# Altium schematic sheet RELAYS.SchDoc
size A4; Revision: V1.2; SheetNumber: 3; SheetTotal: 10
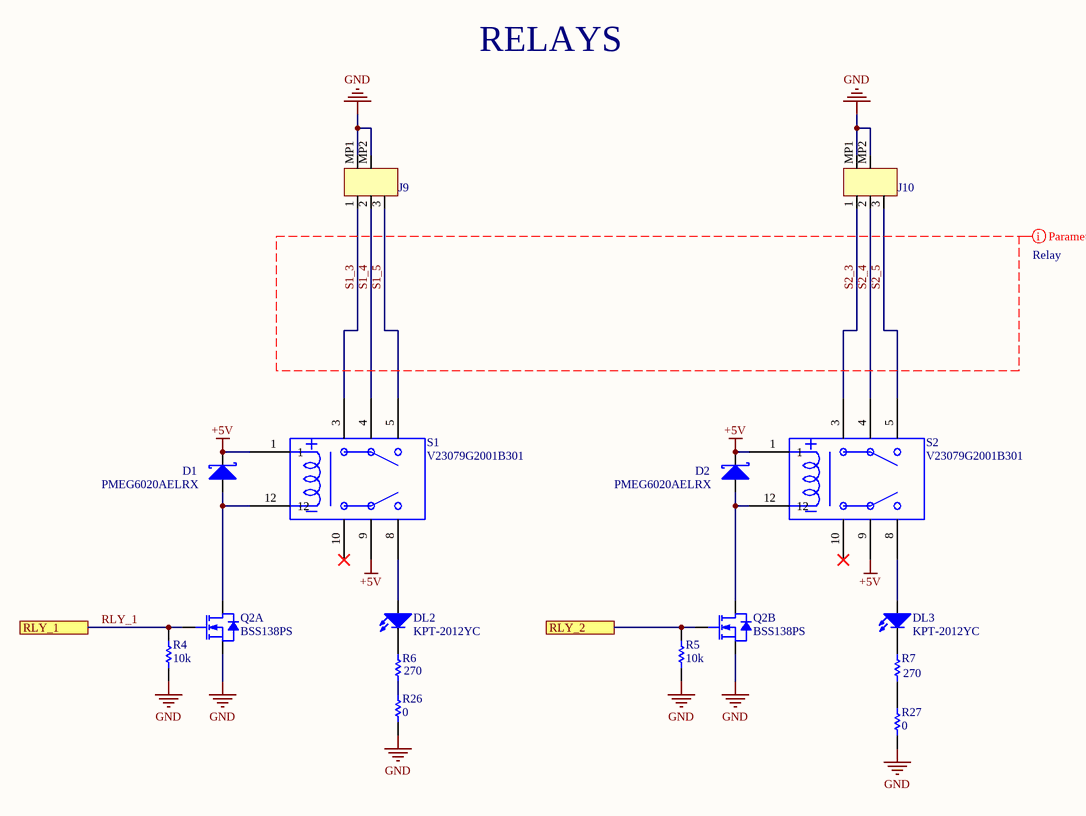
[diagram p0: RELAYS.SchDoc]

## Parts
D1  PMEG6020AELRX  [SOD123-1]
D2  PMEG6020AELRX  [SOD123-1]
DL2  KPT-2012YC  [CHIPLED_0805]
DL3  KPT-2012YC  [CHIPLED_0805]
J9  1771101  [1771101-Footprint-1]  (value not drawn)
J10  1771101  [1771101-Footprint-1]  (value not drawn)
Q2  BSS138PS  [SOT363]  (parts A,B of 2)
R4  value 10k  [RES-0402]  (hidden comment: CRCW040210K0FKED)
R5  value 10k  [RES-0402]  (hidden comment: CRCW040210K0FKED)
R6  value 270  [RES-0402]  (hidden comment: RC0402JR-07270RL)
R7  value 270  [RES-0402]  (hidden comment: RC0402JR-07270RL)
R26  value 0  [RES-0402]  (hidden comment: CRCW04020000Z0EDC)
R27  value 0  [RES-0402]  (hidden comment: CRCW04020000Z0EDC)
S1  V23079G2001B301  [EE2-5NU-L-Footprint-1]
S2  V23079G2001B301  [EE2-5NU-L-Footprint-1]

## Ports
RLY_1, RLY_2

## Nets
+5V: D1.C D2.C S1.1 S1.9 S2.1 S2.9
GND: J9.MP1 J9.MP2 J10.MP1 J10.MP2 Q2.1(S) Q2.4(S) R4.2 R5.2 R26.1 R27.1
RLY_1: Q2.2(G) R4.1 ; port RLY_1
RLY_2: Q2.5(G) R5.1 ; port RLY_2
S1_3: J9.1 S1.3
S1_4: J9.2 S1.4
S1_5: J9.3 S1.5
S2_3: J10.1 S2.3
S2_4: J10.2 S2.4
S2_5: J10.3 S2.5
NetD1_A: D1.A Q2.6(D) S1.12
NetD2_A: D2.A Q2.3(D) S2.12
NetDL2_A: DL2.A S1.8
NetDL2_C: DL2.C R6.2
NetDL3_A: DL3.A S2.8
NetDL3_C: DL3.C R7.2
NetR6_1: R6.1 R26.2
NetR7_1: R7.1 R27.2

Not connected (* = marked no-connect by the designer): S1 10*; S2 10*

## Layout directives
net class Relay: S1_3, S1_4, S1_5, S2_3, S2_4, S2_5

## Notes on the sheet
- RELAYS

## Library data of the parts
D1 D2 = D0026-A.4: DIODE SCHOTTKY SMD 2A 60V SOD123FL; Manufacturer: Nexperia; Manucturer Part Number 2: SS26L; Code Arduino: 2208; Forward Voltage: 0.6V; Manucturer 2: Hottech
DL2 DL3 = L0001-A.3: LED SMD 0805 YELLOW CLEAR; Manufacturer: Kingbright; Code Arduino: 0044
J9 J10 = J0100-A.4: TERM BLK 3P TOP ENTRY 2.5MM SMD; Manufacturer: Phoenix Contact; Current Rating: 6A; Wire Gauge (Min): 20AWG; Number of Positions: 3; Code Arduino: J0100; Wire Gauge (Max): 26AWG; Voltage Rating: 160V; Pitch: 0.098inch; Current: 5A; Number of Levels: 1; Voltage: 150V
Q2 = T0012-A.6: MOSFET N-CH 2x 60V 0.32A SOT363; Manufacturer: Nexperia; Code Arduino: 2323; Device Type: Mosfet 2N-CH SMD
R4 R5 = R0003-A.11: RES CHIP 0402 10K 1% 1/16W; Manufacturer: Vishay; Code Arduino: 0136; Power: 63mW
R6 R7 = R0016-A.11: RES CHIP 0402 270R 5% 1/16W; Manufacturer: Yageo; Power: 63mW; Code Arduino: 2228
R26 R27 = R0000-A.11: RES CHIP 0402 0R 1/16W; Manufacturer: Vishay; Code Arduino: 0039; Power: 63mW; Tolerance: J
S1 S2 = S0009-A.5: RELAY GEN PURP 2A 220VDC 900MHz, DC Input SMT; Part Number: V23079-G2001-B301; Manufacturer: TE Connectivity; Throw Configuration: DPDT; Max Voltage Rating (DC): 220V; Max Voltage Rating (AC): 250V; Number of Poles: 1; Release Time: 1ms; Power Consumption: 140mW; Coil Resistance: 178R; Coil Current: 28mA; Code Arduino: S0009; Coil Type: Non-Latching; Coil Voltage (DC): 5V; Relay Type: General Purpose; Operate Time: 2ms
